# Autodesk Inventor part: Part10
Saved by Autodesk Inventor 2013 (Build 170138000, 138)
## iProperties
Created: 2012-07
Part Number: Part10
Material: Generic
Document SubType Name: Modeling
Designer: Paul
Density: 1 g/cm^3
Author: Paul
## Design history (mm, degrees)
node "User Library-Arduino Mega.SAT1"
body "Solid1"
node "Base1"
